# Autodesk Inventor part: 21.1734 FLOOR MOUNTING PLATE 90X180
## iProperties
Created: 2007-04
Part Number: 21.1734 FLOOR MOUNTING PLATE 90X180
Material: Aluminum-6061
Document SubType Name: Modeling
Designer: Andy Moles
Description: 20.1016 32X180 L = 7.87"
Density: 2.71 g/cm^3
Author: Andy Moles
Title: 20.1016 32X180 L = 7.87"
Subject: 20.1016 32X180 L = 7.87"
Comments: 20.1016 32X180 L = 7.87"
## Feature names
1. Extrusion1
2. Extrusion2
